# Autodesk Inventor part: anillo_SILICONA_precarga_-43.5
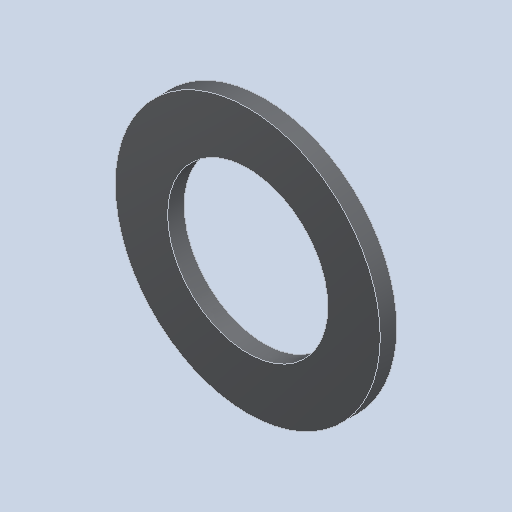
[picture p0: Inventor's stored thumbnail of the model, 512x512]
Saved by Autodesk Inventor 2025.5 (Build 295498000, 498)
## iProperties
Created: 2026-10
Part Number: anillo_SILICONA_precarga_-43.5
Material: Genérico
Document SubType Name: Modeling
Designer: Luis M
Density: 1 g/cm^3
Appearance: Valor por defecto
Author: Luis M
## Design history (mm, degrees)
feature "Base1"
node "Sólido1"
